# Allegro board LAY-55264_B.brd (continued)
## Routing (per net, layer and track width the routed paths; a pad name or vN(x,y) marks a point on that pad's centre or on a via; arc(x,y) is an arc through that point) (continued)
MIPI_DSI1_DATA0_N: length 64.1
  TOP w0.114: U1.44 36.95,43.61 36.95,43.46 37.35,43.07 37.35,42.54 37.07,42.26 35.99,42.26 35.88,42.14 35.88,41.69 35.99,41.57 37.07,41.57 37.35,41.29 37.35,40.59 37.07,40.3 35.99,40.3 35.88,40.19 35.88,39.73 35.99,39.62 37.07,39.62 37.35,39.33 37.35,38.63 37.07,38.35 35.99,38.35 35.88,38.23 35.88,37.78 35.99,37.66 37.07,37.66 37.35,37.38 37.35,36.68 37.07,36.39 35.99,36.39 35.88,36.28 35.88,35.82 35.99,35.71 37.07,35.71 37.35,35.42 37.35,34.11 37.85,33.61 37.85,33.2 37.11,32.47 37.11,32.31 37.44,31.99 37.6,31.99 38.33,32.72 38.74,32.72 40.69,30.77 40.69,24.61 41.07,24.23 41.64,24.23 41.92,23.94 41.92,22.38 42.04,22.26 42.49,22.26 42.61,22.38 42.61,23.94 42.89,24.23 43.59,24.23 43.88,23.94 43.88,22.38 43.99,22.26 44.45,22.26 44.57,22.38 44.57,23.94 44.85,24.23 45.55,24.23 45.84,23.94 45.84,22.38 45.95,22.26 46.41,22.26 46.52,22.38 46.52,23.94 46.81,24.23 47.51,24.23 47.79,23.94 47.79,22.38 47.91,22.26 48.36,22.26 48.48,22.38 48.48,23.94 48.76,24.23 50.73,24.23 51.23,23.72 51.23,20.49 v2(51.53,20.19)
  BOTTOM w0.114: v2(51.53,20.19) 51.24,20.48 51.24,20.64 51.49,20.9 J2.A2
MIPI_DSI1_DATA0_P: length 64.1
  TOP w0.114: U1.43 36.6,43.26 36.75,43.26 37.06,42.95 37.06,42.66 36.94,42.55 35.87,42.55 35.59,42.27 35.59,41.57 35.87,41.28 36.94,41.28 37.06,41.17 37.06,40.71 36.94,40.59 35.87,40.59 35.59,40.31 35.59,39.61 35.87,39.32 36.94,39.32 37.06,39.21 37.06,38.75 36.94,38.64 35.87,38.64 35.59,38.35 35.59,37.65 35.87,37.37 36.94,37.37 37.06,37.25 37.06,36.8 36.94,36.68 35.87,36.68 35.59,36.4 35.59,35.7 35.87,35.41 36.94,35.41 37.06,35.3 37.06,33.99 37.56,33.49 37.56,33.33 36.82,32.59 36.82,32.19 37.32,31.69 37.72,31.69 38.46,32.43 38.62,32.43 40.4,30.65 40.4,24.49 40.95,23.94 41.52,23.94 41.63,23.82 41.63,22.26 41.92,21.97 42.62,21.97 42.9,22.26 42.9,23.82 43.02,23.94 43.47,23.94 43.59,23.82 43.59,22.26 43.87,21.97 44.57,21.97 44.86,22.26 44.86,23.82 44.97,23.94 45.43,23.94 45.54,23.82 45.54,22.26 45.83,21.97 46.53,21.97 46.81,22.26 46.81,23.82 46.93,23.94 47.38,23.94 47.5,23.82 47.5,22.26 47.78,21.97 48.48,21.97 48.77,22.26 48.77,23.82 48.88,23.94 50.61,23.94 50.94,23.6 50.94,22.45 50.77,22.28 50.77,21.99 50.94,21.82 50.94,21.53 50.77,21.37 50.77,21.07 50.94,20.91 50.94,20.48 v2(50.65,20.19)
  BOTTOM w0.114: v2(50.65,20.19) 50.95,20.48 50.95,20.64 50.69,20.9 J2.A3
MIPI_DSI1_DATA1_N: length 64.2
  TOP w0.114: v2(47.49,18.97) 47.77,19.24 47.9,19.24 48.83,18.31 51.69,18.31 53.73,20.35 53.73,21.54 53.45,21.83 52.67,21.83 52.56,21.94 52.56,22.4 52.67,22.51 53.45,22.51 53.73,22.8 53.73,23.5 53.45,23.78 52.67,23.78 52.56,23.9 52.56,24.35 52.67,24.47 53.45,24.47 53.73,24.75 53.73,30.98 48.32,36.39 47.91,36.39 46.88,35.36 46.72,35.36 46.39,35.68 46.39,35.84 47.43,36.88 47.43,37.28 46.93,37.78 46.53,37.78 44.93,36.18 44.77,36.18 44.45,36.5 44.45,36.67 46.04,38.26 46.04,38.67 45.55,39.16 45.15,39.16 43.55,37.56 43.39,37.56 43.07,37.88 43.07,38.05 44.66,39.65 44.66,40.05 44.17,40.54 43.76,40.54 42.72,39.51 42.56,39.51 42.24,39.83 42.24,39.99 43.28,41.03 43.28,41.43 42.87,41.84 41.4,41.84 38.37,44.88 38.37,45.03 U1.48
  BOTTOM w0.114: v2(47.49,18.97) 47.78,19.25 48.29,19.25 48.84,19.8 48.84,20.64 49.09,20.9 J2.A5
MIPI_DSI1_DATA1_P: length 64.2
  TOP w0.114: v2(47.49,19.85) 47.79,19.55 48,19.55 48.17,19.38 48.34,19.38 48.51,19.56 48.69,19.56 48.84,19.4 48.84,19.24 48.66,19.06 48.66,18.9 48.95,18.61 51.57,18.61 53.44,20.47 53.44,21.42 53.33,21.53 52.55,21.53 52.26,21.82 52.26,22.52 52.55,22.8 53.33,22.8 53.44,22.92 53.44,23.38 53.33,23.49 52.55,23.49 52.26,23.78 52.26,24.47 52.55,24.76 53.33,24.76 53.44,24.87 53.44,27.26 53.29,27.41 53.29,27.72 53.44,27.87 53.44,28.18 53.29,28.33 53.29,28.63 53.44,28.78 53.44,29.09 53.29,29.24 53.29,29.55 53.44,29.7 53.44,30.01 53.29,30.15 53.29,30.46 53.44,30.61 53.44,30.85 48.2,36.1 48.03,36.1 47,35.06 46.59,35.06 46.1,35.56 46.1,35.96 47.14,37 47.14,37.16 46.81,37.48 46.65,37.48 45.05,35.89 44.65,35.89 44.16,36.38 44.16,36.79 45.75,38.38 45.75,38.54 45.43,38.87 45.27,38.87 43.67,37.27 43.27,37.27 42.78,37.76 42.78,38.17 44.37,39.77 44.37,39.93 44.04,40.25 43.88,40.25 42.85,39.21 42.44,39.21 41.95,39.71 41.95,40.11 42.98,41.15 42.98,41.31 42.75,41.55 41.28,41.55 38.16,44.67 38.02,44.67 U1.47
  BOTTOM w0.114: J2.A6 48.29,20.9 48.55,20.64 48.55,19.92 48.17,19.55 47.8,19.55 v2(47.49,19.85)
MIPI_DSI1_DATA2_N: length 63.8
  TOP w0.114: U1.50 39.08,45.73 39.08,45.59 41.15,43.51 43.1,43.51 55.06,31.54 55.06,20.1 52.12,17.15 51.58,17.15 51.47,17.04 51.47,16.21 51.19,15.93 50.49,15.93 50.2,16.21 50.2,17.04 50.09,17.15 49.63,17.15 49.51,17.04 49.51,16.21 49.23,15.93 48.53,15.93 48.24,16.21 48.24,17.04 48.13,17.15 47.67,17.15 47.56,17.04 47.56,16.24 47.27,15.96 46.58,15.96 46.29,16.25 46.29,17.91 46.17,18.02 45.83,18.02 45.7,17.9 45.7,16.29 45.41,16.01 44.72,16.01 44.43,16.29 44.43,17.04 44.32,17.15 43.68,17.15 41.57,19.26 41.39,19.26 v2(41.09,18.97)
  BOTTOM w0.114: v2(41.09,18.97) 41.38,19.25 41.92,19.25 42.44,19.78 42.44,20.64 42.69,20.9 J2.A13
MIPI_DSI1_DATA2_P: length 63.7
  TOP w0.114: U1.49 38.72,45.38 38.87,45.38 41.03,43.22 42.97,43.22 54.77,31.42 54.77,20.22 52,17.45 51.46,17.45 51.18,17.16 51.18,16.33 51.06,16.22 50.61,16.22 50.49,16.33 50.49,17.16 50.21,17.45 49.51,17.45 49.22,17.16 49.22,16.33 49.11,16.22 48.65,16.22 48.54,16.33 48.54,17.16 48.25,17.45 47.55,17.45 47.27,17.16 47.27,16.36 47.15,16.25 46.7,16.25 46.58,16.37 46.58,18.03 46.29,18.32 45.71,18.32 45.41,18.02 45.41,16.41 45.29,16.3 44.84,16.3 44.72,16.41 44.72,17.16 44.44,17.45 43.8,17.45 43,18.25 43,18.41 43.14,18.55 43.14,18.72 42.98,18.88 42.81,18.88 42.67,18.74 42.51,18.74 42.35,18.9 42.35,19.06 42.49,19.2 42.49,19.36 42.33,19.52 42.17,19.52 42.03,19.38 41.87,19.38 41.69,19.55 41.39,19.55 v2(41.09,19.85)
  BOTTOM w0.114: v2(41.09,19.85) 41.4,19.55 41.8,19.55 42.15,19.9 42.15,20.64 41.89,20.9 J2.A14
MIPI_DSI1_DATA3_N: length 64.1
  TOP w0.114: v2(38.69,18.97) 38.99,19.26 39.28,19.26 39.44,19.1 39.44,17.92 42.63,14.73 54.76,14.73 56.21,16.18 56.21,32.37 43.51,45.06 41.01,45.06 39.78,46.29 39.78,46.44 U1.52
  BOTTOM w0.114: J2.A16 40.29,20.9 40.04,20.64 40.04,19.76 39.53,19.25 38.98,19.25 v2(38.69,18.97)
MIPI_DSI1_DATA3_P: length 64.1
  TOP w0.114: v2(38.69,19.85) 38.99,19.55 39.4,19.55 39.74,19.22 39.74,18.04 40.66,17.12 40.82,17.12 41.01,17.31 41.18,17.31 41.34,17.15 41.34,16.99 41.14,16.8 41.14,16.63 42.75,15.03 42.97,15.03 43.17,15.22 43.53,15.22 43.73,15.03 44.07,15.03 44.26,15.22 44.63,15.22 44.82,15.03 45.16,15.03 45.36,15.22 45.72,15.22 45.92,15.03 54.64,15.03 55.92,16.31 55.92,32.24 43.39,44.77 40.89,44.77 39.58,46.09 39.43,46.09 U1.51
  BOTTOM w0.114: J2.A17 39.49,20.9 39.75,20.64 39.75,19.88 39.41,19.55 39,19.55 v2(38.69,19.85)
MIPI_DSI1_TS_INT_B: length 48.3
  TOP w0.137: R7.2 v2(27.99,45.65)
  L4_MIX_2 w0.14: v2(45.89,20.66) 45.64,20.41 45.64,19.73 41.19,15.28 37.09,15.28 35.97,16.41 35.97,20.27 v2(36.3,20.6)
  BOTTOM w0.137: v2(36.3,20.6) 36.3,25.85 27.51,34.64 27.51,45.16 v2(27.99,45.65) ; v2(45.89,20.66) J2.A9
MIPI_DSI1_TS_SCL: length 52.3
  BOTTOM w0.137: v1(11.84,43.81) 13.78,43.81 32.57,25.03 32.57,19.79 37.09,15.28 40.84,15.28 44.58,19.01 44.58,20.32 44.29,20.6 J2.A11
MIPI_DSI1_TS_SDA: length 56.4
  BOTTOM w0.137: J2.A10 45.09,20.56 44.89,20.36 44.89,18.88 40.97,14.96 36.96,14.96 32.26,19.66 32.26,24.89 14.1,43.05 11.63,43.05 11.34,43.35 11.34,45.85 v1(11.84,46.35)
MIPI_DSI_EN: length 30.9
  TOP w0.137: v2(50.04,52.83) 49.66,52.45 U9.2 ; U2.4 v2(32.91,34.3)
  L4_MIX_2 w0.14: v2(50.04,52.83) 49.28,52.07 49.28,46.59 41.04,38.35 36.96,38.35 v2(32.91,34.3)
  BOTTOM w0.137: v2(32.91,34.3) 32.88,34.27 U8.1
PMIC_PG: length 84.5
  TOP w0.137: U6.18 140.76,38.62 140.91,38.46 R74.2 v1(142.63,38.46) ; U5.1 v2(76.6,42.63) 76.2,43.03 76.2,44.15 77.2,45.15 U7.1
  L4_MIX_2 w0.14: v2(76.6,42.63) 76.6,41.61 79.48,38.73 v2(95.63,38.73)
  BOTTOM w0.137: v2(95.63,38.73) 96.77,38.73 97.54,39.5 121.54,39.5 123.06,37.97 136.53,37.97 137.8,36.7 139.95,36.7 141.71,38.46 v1(142.63,38.46)
PRE_COMP_RC: length 1
  TOP w0.254: C87.1 R63.2
SW_CT: length 2.1
  TOP w0.137: C83.1 55.24,69.25 55.24,68.45 55.69,68.01 U10.4
SW_QOD: length 3.3
  TOP w0.508: R70.1 54.28,68.4 54.74,67.94 54.74,67.56 55.25,67.06 U10.5
N20060287: length 7.3
  TOP w0.137: X1.1 36.01,59.5 36.2,59.31 36.2,56.64 C19.1 34.59,55.04 34.59,54.46 U1.15
N20060288: length 4.7
  TOP w0.137: U1.16 34.16,54.18 34.16,55.24 C18.1 32.94,56.47 X1.3
N20069061: length 4.3
  BOTTOM w0.137: J8.B8 112.29,26.94 113.03,27.69 R52.1
N20069073: length 4.2
  BOTTOM w0.137: J8.B9 111.49,26.91 112.01,27.43 R53.1
N20082822: length 1.8
  TOP w0.137: D1.C v2(58.29,38.48)
  BOTTOM w0.137: R25.2 v2(58.29,38.48)
N20082834: length 13.3
  TOP w0.137: Q1.3 v2(54.2,43.31)
  BOTTOM w0.137: R25.1 55.88,37.97 52.2,37.97 50.73,39.44 50.73,40.95 53.09,43.31 v2(54.2,43.31)
N20083165: length 1.8
  TOP w0.137: v2(58.27,36.07) 58.28,36.06 D2.C
  BOTTOM w0.137: R26.2 v2(58.27,36.07)
N20083177: length 19.6
  BOTTOM w0.137: Q2.3 55.21,44.54 54.61,43.94 52.96,43.94 50.42,41.4 50.42,39.12 52.07,37.46 54.99,37.46 R26.1
N20083959: length 3.5
  TOP w0.137: Q3.3 53.33,47.03 v2(52.88,46.58)
  BOTTOM w0.137: R28.2 52.88,46.18 v2(52.88,46.58) 53.2,46.9 Q2.1
N20084103: length 2.7
  TOP w0.137: R29.2 R23.2 Q1.1
N20084118: length 2.6
  TOP w0.137: R31.2 R24.2 Q3.1
N20098940: length 1.8
  TOP w0.137: R37.1 80.17,44.52 80.17,44.37 U5.4
N20105492: length 1.8
  TOP w0.137: D3.C v2(139.88,12.58)
  BOTTOM w0.137: R47.2 v2(139.88,12.58)
N20105494: length 1.8
  TOP w0.137: D4.C v2(139.88,10.17)
  BOTTOM w0.137: R48.2 v2(139.88,10.17)
N20105548: length 3.1
  BOTTOM w0.137: Q4.3 136.67,11.34 R47.1
N20105560: length 11
  TOP w0.137: v2(137.03,10.17) 137.03,13.82 135.74,15.11 v2(135.74,18.96)
  BOTTOM w0.137: R48.1 v2(137.03,10.17) ; Q5.3 v2(135.74,18.96)
N20105562: length 3.3
  BOTTOM w0.137: Q4.1 132.35,10.4 131.95,10.79 131.95,10.79 131.83,10.92 R50.2 R45.2
N20105564: length 2.9
  BOTTOM w0.137: 126.75,17.14 127.89,17.14 127.89,17.66 127.81,17.74 Q6.1
N20105588: length 4.3
  BOTTOM w0.137: Q5.1 R49.2 130.8,18.84 129.87,19.78 Q6.3
N20114256: length 2
  TOP w0.137: R57.2 R58.1 C73.1
N20115373: length 3.9
  TOP w0.137: R65.1 142.6,32.75 R67.2 143.38,32 143.89,32 144.27,31.62 TP15.1
N20115434: length 8
  TOP w0.137: R66.1 142.6,33.76 R68.2 v2(142.62,34.54) ; TP17.1 v2(144.27,29.91)
  BOTTOM w0.137: v2(144.27,29.91) 144.27,31.37 142.62,33.02 v2(142.62,34.54)
N20116336: length 2
  TOP w0.137: U6.19 140.49,39.12 140.6,39.01 141.12,39.01 R75.2
N20169094: length 3.2
  TOP w0.137: R54.2 109.47,19.58 v2(109.14,19.91)
  BOTTOM w0.137: v2(109.14,19.91) 109.49,20.26 J8.A11
N20198038: length 2.9
  BOTTOM w0.137: U8.4 34.18,30.7 34.32,30.57 35.52,30.57 35.69,30.73 R15.1
N20266401: length 2.8
  TOP w0.137: v2(20.23,25.91) 20.23,25.43 20.07,25.27 TP25.1
  BOTTOM w0.137: J1.B10 v2(20.23,25.91)
N20266443: length 3
  TOP w0.137: v2(45.49,26.13) 45.11,26.13 TP27.1
  BOTTOM w0.137: J2.B10 v2(45.49,26.13)
N20266627: length 2.5
  TOP w0.137: v2(85.02,20.62) 85.85,21.45 TP26.1
  BOTTOM w0.137: J7.A10 v2(85.02,20.62)
N20266649: length 2.8
  TOP w0.137: v2(110.29,20.57) TP28.1
  BOTTOM w0.137: TP28.1 v2(110.29,20.57)
N20266684: length 8.6
  TOP w0.137: TP29.1 129.79,37.59 131.32,39.12 U6.52
N20266708: length 8.9
  TOP w0.137: TP30.1 130.81,32 130.81,32.77 130.3,33.27 130.3,37.21 131.21,38.12 U6.54
N20266714: length 6.2
  TOP w0.137: U6.55 131.34,37.62 130.81,37.08 130.81,33.66 TP31.1
N20267097: length 3.5
  TOP w0.137: U6.56 131.61,37.12 131.32,36.83 131.32,34.8 TP32.1
N20272842: length 1.8
  TOP w0.137: D7.C v2(58.32,41.54)
  BOTTOM w0.137: v2(58.32,41.54) 57.42,41.54 R87.2
N20272854: length 2.9
  BOTTOM w0.137: R87.1 53.48,41.53 Q8.3
N20272867: length 2.5
  TOP w0.137: R88.1 55.09,39.62 55.24,39.78 v2(55.63,39.78)
  BOTTOM w0.137: v2(55.63,39.78) 55.36,39.51 Q8.1
N20273152: length 1.8
  TOP w0.137: D8.C 58.35,46.39 v2(58.32,46.35)
  BOTTOM w0.137: R89.2 v2(58.32,46.35)
N20273623: length 1.8
  TOP w0.137: D9.C v2(139.85,14.99)
  BOTTOM w0.137: R90.2 v2(139.85,14.99)
N20273625: length 2
  TOP w0.137: D10.C v2(139.97,21.05)
  BOTTOM w0.137: R91.2 139.74,20.83 v2(139.97,21.05)
N20273637: length 2.9
  BOTTOM w0.137: R90.1 137.04,15.86 Q9.3
N20273680: length 1.4
  BOTTOM w0.137: R92.1 131.9,14.93 Q9.1
N20273951: length 1.9
  TOP w0.137: D11.C v2(139.97,19.4)
  BOTTOM w0.137: R93.2 v2(139.97,19.4)
N20274335: length 1.8
  TOP w0.137: v2(58.32,48.77) 58.36,48.81 D12.C
  BOTTOM w0.137: R94.2 v2(58.32,48.77)
N20274920: length 1.8
  TOP w0.137: D13.C v2(139.85,17.41)
  BOTTOM w0.137: R95.2 v2(139.85,17.41)
N20275554: length 1.8
  TOP w0.137: D14.C 59.15,43.94 v2(58.32,43.94)
  BOTTOM w0.137: v2(58.32,43.94) R96.2
N20319150: length 2.9
  TOP w0.137: R99.1 J13.2
N20319151: length 2.8
  TOP w0.137: R107.1 J13.4
N20319153: length 2.8
  TOP w0.137: R109.1 J13.6
N20319312: length 3.2
  TOP w0.137: R108.2 J13.5
N20319313: length 3.2
  TOP w0.137: R100.2 J13.3
N20319314: length 3.2
  TOP w0.137: R98.2 J13.1
N20319786: length 2.8
  TOP w0.137: R104.2 J14.1
N20319788: length 2.8
  TOP w0.137: R101.1 127.89,3.94
N20319806: length 2.8
  TOP w0.137: R105.2 J14.3
N20319808: length 2.8
  TOP w0.137: R102.1 127.89,6.48
N20319814: length 2.8
  TOP w0.137: R106.2 130.43,9.02
N20319816: length 2.8
  TOP w0.137: R103.1 127.89,9.02
N20331689: length 3.5
  TOP w0.137: U7.4 78.5,55.86 R112.1 R110.2 R111.2
N20347583: length 1.8
  TOP w0.137: U9.4 v2(51.96,51.8)
  BOTTOM w0.137: R69.1 52.45,51.82 52.43,51.8 v2(51.96,51.8)
N2022936611: length 9
  TOP w0.137: v2(143.82,41.03) 143.82,41.33 TP33.1 ; v2(138.15,37.29) U6.12
  BOTTOM w0.137: v2(138.15,37.29) 139.58,37.29 142.57,40.28 143.07,40.28 v2(143.82,41.03)
N2022936612: length 6.7
  TOP w0.137: U6.13 138.65,35.82 138.81,35.66 139,35.66 139.61,35.05 143.76,35.05 TP34.1
N2022936613: length 8.1
  TOP w0.137: U6.14 139.15,35.9 139.61,35.45 143.14,35.45 143.89,36.19 143.89,37.97 TP35.1
N2022936614: length 8.9
  TOP w0.137: U6.15 140.39,37.12 140.53,36.98 140.53,36.43 141.18,35.78 143.03,35.78 143.57,36.32 143.57,38.91 143.77,39.11 143.77,39.76 TP36.1
N2022936615: length 9.4
  TOP w0.137: U6.16 140.51,37.62 140.84,37.29 140.84,36.56 141.31,36.09 142.9,36.09 143.26,36.45 143.26,39.04 143.45,39.24 143.45,40.19 TP37.1
N2022936623: length 5.5
  TOP w0.137: U6.24 140.5,41.62 140.69,41.8 143.15,41.8 144.15,42.8 TP38.1
N2022936624: length 3.2
  TOP w0.137: TP39.1 142.07,42.12 U6.25
N2022936625: length 5.1
  TOP w0.137: TP40.1 141.3,42.62 U6.26
N2022936626: length 3.2
  TOP w0.137: U6.27 140.65,43.12 TP41.1
N2022936627: length 6.5
  TOP w0.137: TP42.1 142.88,46.48 140.84,44.45 140.84,43.94 140.52,43.62 U6.28
N2022936628: length 6.2
  TOP w0.137: U6.29 139.15,44.79 139.45,45.09 140.97,45.09 TP43.1
N2022936629: length 4.8
  TOP w0.137: U6.30 138.65,44.8 139.25,45.4 140.27,45.4 TP44.1
N2022936630: length 8.5
  TOP w0.137: U6.31 138.15,44.8 141.35,48.01 142.37,48.01 143.51,49.15 TP45.1
N2022936631: length 6.3
  TOP w0.137: TP46.1 141.73,48.83 137.65,44.75 U6.32
N2022936633: length 9.5
  TOP w0.137: U6.34 136.65,44.83 138.68,46.86 138.68,48.2 140.65,50.16 TP47.1
N2022936634: length 8.8
  TOP w0.137: U6.35 136.15,44.84 138.37,47.06 138.37,48.33 TP48.1

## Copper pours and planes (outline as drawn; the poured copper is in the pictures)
GND on TOP (solid shape): 15.29,64.85 15.29,57.71 15.28,57.65 15.28,57.59 15.28,57.37 15.28,57.31 15.29,57.25 15.29,56.72 15.49,56.52 15.49,55.45 13.69,55.45 13.51,55.63 13.51,60.45 13.44,60.45 13.44,61.98 13.51,61.98 13.51,64.48 13.51,64.85 13.64,64.97 15.16,64.97
GND on BOTTOM (solid shape): 13.67,34.54 13.67,32.99 13.44,32.77 11.71,32.77 11.56,32.92 11.56,34.52 11.76,34.72 13.49,34.72
GND on BOTTOM (solid shape): 15.57,30.91 15.57,29.29 15.42,29.13 13.79,29.13 13.59,29.34 13.59,30.94 13.69,31.04 15.44,31.04
GND on BOTTOM (solid shape): 22.1,30.99 22.1,29.34 21.89,29.13 20.27,29.13 20.07,29.34 20.07,30.99 20.32,31.24 21.84,31.24
GND on BOTTOM (solid shape): 25.27,30.99 25.27,29.34 25.07,29.13 23.44,29.13 23.24,29.34 23.24,30.99 23.49,31.24 25.02,31.24
GND on BOTTOM (solid shape): 40.83,31.04 40.83,29.29 40.68,29.13 39.06,29.13 38.85,29.34 38.85,30.99 39.11,31.24 40.63,31.24
GND on BOTTOM (solid shape): 43.42,30.99 43.42,29.34 43.22,29.13 41.6,29.13 41.39,29.34 41.39,30.99 41.65,31.24 43.17,31.24
GND on BOTTOM (solid shape): 47.36,30.95 47.36,29.34 47.16,29.13 45.53,29.13 45.33,29.34 45.33,30.85 45.59,31.12 47.19,31.12
GND on BOTTOM (solid shape): 49.86,30.96 49.86,29.36 49.63,29.13 48.31,29.13 48.18,29.26 48.18,30.94 48.31,31.06 49.76,31.06
GND on TOP: 110.36,52.36 110.36,39.3 111.12,38.55 111.12,38.31 111.11,38.31 111.11,37.13 113.22,35.02 131.86,35.02 131.86,46.45 130.3,48.01 130.3,49.15 126.53,52.93 110.93,52.93
GND on TOP: 139.95,22.86 143.51,22.86 143.64,22.99 143.64,30.23 143.51,30.35 139.95,30.35 139.7,30.1 139.7,23.11
GND on TOP: 52.78,64.08 52.6,63.91 52.6,62.2 52.83,61.98 55.32,61.98 55.58,62.23 55.58,63.91 55.4,64.08
GND on TOP: 120.4,67.06 124.59,67.06 124.84,66.8 124.84,61.85 124.46,61.47 120.4,61.47 120.14,61.72 120.14,66.8
GND on TOP: 101.93,48.59 102.48,48.59 109,42.07 109,39.21 110.25,37.96 110.25,36.36 112.53,34.07 114.13,34.07 121.92,26.29 121.92,2.74 75.58,2.74 75.58,14.09 75.74,14.25 76.48,14.25 76.15,14.58 75.58,14.58 75.58,38.06 85.67,48.15 86.46,48.15 86.5,48.2 86.51,48.24 86.49,48.34 86.4,48.39 86.25,48.39 87.25,48.39 92.16,43.48 92.5,43.48 96.27,47.25 100.03,47.25 100.24,47.46 100.8,47.46 ; 9 cut-outs
GND on TOP: 133.93,32.64 134.24,32.64 135.15,31.72 135.15,31.47 134.26,30.58 134.01,30.58 133.07,31.52 133.07,31.78
GND on TOP: 111.25,66.29 113.03,68.07 113.03,68.33 113.41,68.71 113.92,68.71 115.19,67.44 115.19,67.06 112.9,64.77 112.52,64.77 111.25,66.04
GND on TOP: 132.44,35.26 133.1,35.26 133.3,35.46 133.3,36.88 133.48,37.06 133.48,37.49 134.11,38.13 138.23,38.13 138.23,39.7 138.3,39.78 139.19,39.78 139.19,40.51 138.33,40.51 138.23,40.61 138.23,42.65 133.76,42.65 133.6,42.49 133.6,38.61 132.49,37.49 132.51,37.46 132.51,35.79 132.33,35.61 132.33,35.36
GND on TOP: 129.16,65.91 130.3,65.91 130.68,66.29 134.24,66.29 135.38,65.15 139.45,65.15 139.95,65.66 139.95,69.09 139.19,69.85 129.29,69.85 129.03,69.6 129.03,66.04
GND on TOP: 20.37,48.77 27.94,48.77 27.94,47.78 30.68,47.78 30.68,48.44 35.64,43.48 35.98,43.48 39.75,47.25 40.23,47.25 40.23,45.59 40.67,45.16 42.21,45.16 42.21,45.42 41.91,45.72 41.91,46.56 41.61,46.86 41.61,47.17 41.68,47.25 46.23,47.25 65.41,28.07 65.41,2.49 9.37,2.49 9.37,37.77 ; 3 cut-outs
GND on TOP: 138.93,50.67 138.93,54.87 138.81,54.99 136.17,54.99 135.97,54.79 135.97,50.6 136.14,50.42 138.68,50.42
GND on TOP: 128.52,24.77 128.52,20.83 128.91,20.45 133.48,20.45 134.11,21.08 134.11,29.72 133.99,29.84 129.79,29.84 129.54,29.59 129.54,25.78
GND on TOP: 58.04,66.75 59.69,66.75 59.99,67.06 64.39,67.06 64.9,67.56 64.9,71.09 64.64,71.35 59.79,71.35 59.56,71.12 59.56,69.85 60.2,69.85 60.32,69.72 60.32,68.45 59.23,67.36 58.04,67.36
GND on BOTTOM: 1.27,79.76 65.41,79.76 65.41,1.27 1.27,1.27 1.27,14.99 55.24,14.99 55.24,35.05 18.03,35.05 17.4,35.69 9.4,35.69 8.74,36.35 8.74,40.03 8.74,36.35 9.4,35.69 9.75,35.69 9.75,38.28 9.78,38.4 9.85,38.51 11.37,40.03 12.16,40.03 12.13,39.91 12.06,39.82 11.42,39.17 11.4,39.1 11.46,39.06 11.51,39.06 11.53,39.07 11.67,39.16 11.84,39.19 12.29,38.73 11.84,38.28 11.66,38.31 11.51,38.41 11.11,38.41 10.71,38.02 10.71,35.69 17.4,35.69 18.03,35.05 21.35,35.05 21.46,35.14 21.43,35.27 15.33,41.37 15.47,41.5 15.47,42.57 13.92,44.12 13.54,44.12 13.36,44.3 13.36,46.28 13.74,46.66 13.54,46.86 9.07,46.86 8.74,47.19 8.74,65.38 1.27,65.38 ; 1 cut-out
GND on BOTTOM: 66.67,79.76 146.05,79.76 146.05,1.27 67.31,1.27 67.31,14.73 94.13,14.73 94.51,14.35 94.51,12.85 95.3,12.07 95.3,9.17 96.44,8.03 99.95,8.03 100.43,8.51 100.43,13.89 101.27,14.73 120.9,14.73 120.9,32 94.16,32 94.44,31.72 94.44,31.42 94.23,31.22 92.99,31.22 92.2,32 66.67,32 ; 2 cut-outs
GND on L2_GND_1, L5_GND_2: 1.27,79.76 146.05,79.76 146.05,1.27 1.27,1.27
GND on L3_MIX_1: 1.65,67.82 7.62,67.82 8.76,66.67 21.72,66.67 21.72,57.02 24.77,53.98 38.86,53.98 39.5,53.34 43.05,53.34 43.81,54.1 43.81,57.28 47.5,60.96 53.85,60.96 53.85,78.23 52.32,79.76 1.27,79.76 1.27,68.2
GND on L3_MIX_1: 66.67,79.76 146.05,79.76 146.05,1.27 66.67,1.27
GND on L4_MIX_2: 10.79,79.76 65.02,79.76 65.02,46.1 49.53,46.1 49.53,53.59 40.31,53.59 40.31,53.72 38.61,55.42 37.06,55.42 36.75,55.12 36.75,53.98 38.58,52.15 38.61,52.15 38.61,48.79 38.43,48.62 32.66,48.62 32.51,48.77 32.51,51.36 33.15,51.99 33.15,53.75 32.26,54.64 26.49,54.64 26.06,54.2 24.97,54.2 24.77,54.41 24.77,58.01 23.04,59.74 17.17,59.74 14.78,57.35 13.26,57.35 10.79,59.82
GND on L4_MIX_2: 68.96,79.76 146.05,79.76 146.05,58.29 103.12,58.29 103.12,51.05 99.39,51.05 97.1,53.34 97.1,55.37 95.33,57.15 92.08,57.15 89.97,55.04 88.04,55.04 87.07,54.08 83.46,54.08 77.85,59.69 77.85,66.93 75.95,68.83 68.96,68.83 ; 1 cut-out
VCC_1V0_SER on TOP (solid shape): 18.15,59.17 18.94,59.17 19.69,58.42 19.69,55.78 19.35,55.45 15.93,55.45 15.85,55.52 15.85,56.39 16.33,56.87 16.33,58.09 15.6,58.83 15.6,60.15 17.17,60.15
VCC_1V0_SER on L4_MIX_2: 20.78,54.91 25.02,50.67 29.79,50.67 31.06,51.94 31.37,51.94 31.98,51.33 31.98,48.11 31.27,47.4 21.34,47.4 16.64,52.1 16.64,57.84 17.53,58.72 19.61,58.72 20.78,57.56
VCC_1V8_LVDS on TOP (solid shape): 89.84,19.79 89.84,18.87 89.59,18.62 89.28,18.62 89.05,18.85 88.01,18.85 87.83,19.02 87.83,20.02 88.01,20.19 89.43,20.19
VCC_1V8_LVDS on TOP (solid shape): 115.1,19.57 115.1,18.87 114.85,18.62 114.54,18.62 114.32,18.85 113.27,18.85 113.1,19.02 113.1,20.18 113.36,20.45 114.22,20.45
VCC_1V8_LVDS on BOTTOM (solid shape): 89.23,22.8 89.23,20.4 89.84,19.79 89.84,18.87 89.58,18.62 88.26,18.62 88.03,18.85 88.03,22.82 88.08,22.87 89.15,22.87
VCC_1V8_LVDS on BOTTOM (solid shape): 114.49,22.8 114.49,20.18 115.1,19.57 115.1,18.87 114.85,18.62 113.53,18.62 113.3,18.85 113.3,22.82 113.35,22.87 114.41,22.87
VCC_1V8_LVDS on TOP: 133.15,48.97 135.51,48.97 135.51,55.02 135.03,55.5 132.92,55.5 132.46,55.04 132.46,49.66
VCC_1V8_LVDS on BOTTOM: 132.59,50.16 135.26,50.16 135.51,50.42 135.51,55.02 135.03,55.5 132.92,55.5 132.46,55.04 132.46,50.29
VCC_1V8_LVDS on L3_MIX_1: 129.54,12.07 132.21,9.4 132.21,3.3 132.59,2.92 135.26,2.92 135.76,3.43 135.76,12.07 133.6,14.22 131.06,14.22 129.54,12.7
VCC_1V8_LVDS on L3_MIX_1: 69.98,36.68 69.98,26.8 77.09,26.8 77.09,22.48 84.33,22.48 84.33,18.67 115.82,18.67 127.64,30.48 127.64,37.08 139.32,37.08 139.32,59.18 102.62,59.18 102.62,52.96 101.73,52.07 100.46,52.07 98.3,54.23 98.3,56.52 95.63,59.18 88.14,59.18 86.44,57.48 86.44,53.92 85.47,52.96 81.38,52.96 80.52,53.82 80.52,55.98 80.19,56.31 78.16,56.31 77.72,55.88 77.72,39.98 75.18,37.44 70.74,37.44
VCC_1V8_MIPI on TOP (solid shape): 13.21,58.08 13.18,58.07 13.14,58.02 13.13,57.96 13.13,57.76 13.14,57.7 13.18,57.66 13.21,57.64 13.21,55.58 13.08,55.45 11.25,55.45 11.02,55.68 11.02,57.81 11.73,58.52 11.73,60.02 11.86,60.15 13.21,60.15
VCC_1V8_MIPI on BOTTOM (solid shape): 24.61,28.4 24.61,26.87 24.43,26.69 24.43,23.65 24.38,23.6 23.32,23.6 23.24,23.67 23.24,26.09 22.58,26.75 22.58,28.24 22.86,28.52 24.49,28.52
VCC_1V8_MIPI on BOTTOM (solid shape): 49.78,28.32 49.78,26.78 49.7,26.69 49.7,23.65 49.65,23.6 48.58,23.6 48.5,23.67 48.5,26.25 47.88,26.87 47.88,28.37 48.03,28.52 49.58,28.52
VCC_1V8_MIPI on L3_MIX_1: 1.91,65.66 17.78,65.66 19.18,67.06 19.18,72.77 19.43,73.02 21.21,73.02 21.46,72.77 21.46,56.39 24.38,53.47 38.61,53.47 39.37,52.7 43.18,52.7 44.45,53.98 44.45,57.15 47.62,60.32 53.85,60.32 53.85,27.05 47.62,27.05 47.62,29.08 26.29,29.08 26.29,26.8 22.35,26.8 22.35,29.08 1.91,29.08
VCC_3V3_LVDS on TOP (solid shape): 83.31,19.91 83.31,18.75 83.19,18.62 82.88,18.62 82.65,18.85 81.61,18.85 81.43,19.02 81.43,20.02 81.61,20.19 83.03,20.19
VCC_3V3_LVDS on TOP (solid shape): 108.7,19.77 108.7,18.87 108.45,18.62 108.14,18.62 107.92,18.85 106.87,18.85 106.7,19.02 106.7,20.02 106.87,20.19 108.28,20.19
VCC_3V3_LVDS on BOTTOM (solid shape): 82.83,22.8 82.83,20.45 83.44,19.84 83.44,18.87 83.18,18.62 81.86,18.62 81.63,18.85 81.63,22.82 81.68,22.87 82.75,22.87
VCC_3V3_LVDS on BOTTOM (solid shape): 108.09,22.8 108.09,20.38 108.7,19.77 108.7,18.87 108.45,18.62 107.13,18.62 106.9,18.85 106.9,22.82 106.95,22.87 108.01,22.87
VCC_3V3_LVDS on TOP: 136.4,32.38 136.02,32 136.02,29.84 135.13,28.96 135.13,22.1 135.38,21.84 138.81,21.84 139.07,22.1 139.07,32.38
VCC_3V3_LVDS on L3_MIX_1: 69.98,26.29 69.98,9.65 145.67,9.65 145.67,42.04 139.83,42.04 139.83,37.08 139.45,36.7 128.02,36.7 128.02,30.1 116.08,18.16 110.49,18.16 110.49,20.32 107.06,20.32 107.06,18.16 83.82,18.16 83.82,21.97 76.58,21.97 76.58,26.29
VCC_3V3_MIPI on BOTTOM (solid shape): 43.42,28.22 43.42,26.34 43.3,26.21 43.3,23.65 43.25,23.6 42.18,23.6 42.1,23.67 42.1,26.77 42,26.87 41.62,26.87 41.4,27.09 41.4,28.33 41.6,28.52 43.12,28.52
VCC_3V3_MIPI on BOTTOM (solid shape): 18.16,34.04 18.16,26.29 18.03,26.16 18.03,23.65 17.98,23.6 16.92,23.6 16.84,23.67 16.84,26.11 16.13,26.82 16.13,31.62 15.75,32 14.48,32 14.22,32.26 14.22,32.89 14.22,33.91 14.22,34.57 14.38,34.72 17.48,34.72
VCC_3V3_MIPI on L4_MIX_2: 40.64,22.86 64.14,22.86 64.14,45.59 49.28,45.59 39.88,36.2 11.56,36.2 11.56,30.35 40.39,30.35 40.64,30.1 ; 1 cut-out
VCC_5V0_LVDS on TOP (solid shape): 80.7,20.02 80.7,18.97 80.57,18.85 79.65,18.85 79.43,18.62 78.87,18.62 78.61,18.87 78.61,19.91 78.89,20.19 80.52,20.19
VCC_5V0_LVDS on TOP (solid shape): 105.96,20.02 105.96,18.97 105.83,18.85 104.92,18.85 104.69,18.62 104.13,18.62 103.88,18.87 103.88,19.78 104.29,20.19 105.78,20.19
VCC_5V0_LVDS on BOTTOM (solid shape): 80.42,22.82 80.42,18.85 80.19,18.62 78.87,18.62 78.61,18.87 78.61,19.91 79.22,20.52 79.22,22.8 79.3,22.87 80.37,22.87
VCC_5V0_LVDS on BOTTOM (solid shape): 105.68,22.82 105.68,18.85 105.45,18.62 104.13,18.62 103.88,18.87 103.88,19.78 104.49,20.39 104.49,22.8 104.56,22.87 105.63,22.87
VCC_5V0_LVDS on TOP: 136.09,48.01 137.54,48.01 137.74,47.8 137.74,46.69 135.89,44.83 135.89,43.94 135.51,43.94 135.51,45.21 135.76,45.47 135.76,45.59 135.94,45.77 135.94,47.85
VCC_5V0_LVDS on TOP: 135,36.83 135,35.94 134.8,35.74 134.8,34.72 134.98,34.54 134.98,33.4 135.76,32.61 136.14,32.61 136.47,32.94 136.47,33.43 135.64,34.26 135.64,34.95 135.28,35.31 135.28,36.86 135.26,36.88 135.05,36.88
VCC_5V0_LVDS on TOP, BOTTOM: 110.49,53.47 110.74,53.21 116.2,53.21 116.2,57.4 115.7,57.91 111.28,57.91 110.49,57.12
VCC_5V0_LVDS on L4_MIX_2: 111.38,57.91 144.65,57.91 144.65,6.1 78.61,6.1 78.61,20.57 83.24,20.57 84.07,19.74 84.07,13.34 99.57,13.34 102.67,16.43 102.67,16.92 102.62,16.97 102.62,19.51 103.17,20.07 105.92,20.07 105.92,13.34 128.52,13.34 128.52,36.7 130.68,38.86 130.68,40.64 123.19,40.64 123.19,49.4 111.38,49.4
VCC_5V0_MIPI on BOTTOM (solid shape): 15.62,28.35 15.62,23.65 15.57,23.6 14.5,23.6 14.43,23.67 14.43,26.77 14.33,26.87 13.74,26.87 13.59,27.03 13.59,28.35 13.77,28.52 15.44,28.52
VCC_5V0_MIPI on BOTTOM (solid shape): 40.88,28.35 40.88,23.65 40.83,23.6 39.77,23.6 39.69,23.67 39.69,26.77 39.59,26.87 39.01,26.87 38.85,27.03 38.85,28.35 39.03,28.52 40.71,28.52
VCC_5V0_MIPI on L4_MIX_2: 40,29.46 40,22.89 11.56,22.89 11.56,28.52 23.49,28.52 24.43,29.46
VCC_12V0 on TOP: 117.09,67.56 124.59,67.56 124.71,67.69 124.71,74.04 124.33,74.42 122.17,74.42 121.92,74.17 121.92,71.55 121.11,70.74 117.35,70.74 116.97,70.36 116.97,67.69
VCC_12V0_DESCONN on TOP: 111.51,74.17 120.9,74.17 121.16,73.91 121.16,71.5 120.78,71.12 115.19,71.12 108.99,64.92 106.55,64.92 106.02,65.46 106.02,68.68
VCC_12V0_DESCONN on BOTTOM: 114.81,70.74 121.16,70.74 121.54,71.12 121.54,73.66 121.03,74.17 111.51,74.17 105.92,68.58 105.92,65.53 106.55,64.9 108.97,64.9
VCC_12V0_EXT on TOP, BOTTOM: 128.83,65.48 133.91,65.48 135.51,63.88 139.57,63.88 140.08,63.37 140.08,59.82 139.7,59.44 127.13,59.44 125.09,61.47 125.09,74.17 125.35,74.42 128.02,74.42 128.65,73.79 128.65,65.66
VCC_12V0_LVDS on TOP (solid shape): 112.36,20.02 112.36,18.97 112.23,18.85 111.28,18.85 111.05,18.62 110.53,18.62 110.28,18.87 110.28,19.91 110.56,20.19 112.18,20.19
VCC_12V0_LVDS on TOP (solid shape): 87.1,20.02 87.1,18.97 86.97,18.85 86.05,18.85 86,18.8 85.98,18.8 85.98,18.77 85.83,18.62 85.37,18.62 85.19,18.8 85.19,19.89 85.5,20.19 86.92,20.19
VCC_12V0_LVDS on BOTTOM (solid shape): 86.82,22.82 86.82,18.85 86.59,18.62 85.27,18.62 85.01,18.87 85.01,19.91 85.62,20.52 85.62,22.8 85.7,22.87 86.77,22.87
VCC_12V0_LVDS on BOTTOM (solid shape): 112.08,22.82 112.08,18.85 111.85,18.62 110.53,18.62 110.28,18.87 110.28,19.91 110.89,20.52 110.89,22.8 110.96,22.87 112.03,22.87
VCC_12V0_LVDS on TOP: 132.38,40.26 132.38,39.47 131.17,39.47 129.41,37.72 129.41,33.4 127.76,31.75 127.76,20.83 127.38,20.45 123.57,20.45 123.32,20.7 123.32,27.18 119.76,30.73 119.76,34.8 120.27,35.31 124.46,35.31 125.35,36.2 125.35,36.96 128.65,40.26
VCC_12V0_LVDS on TOP, BOTTOM: 119.38,61.47 119.63,61.72 119.63,65.15 119.38,65.41 114.17,65.41 113.41,64.64 113.41,61.85 113.79,61.47
VCC_12V0_LVDS on L4_MIX_2: 109.6,65.91 119.25,65.91 119.53,65.63 119.53,58.29 110.74,58.29 110.74,49.02 122.81,49.02 122.81,40.26 130.2,40.26 130.2,38.91 128.14,36.86 128.14,13.84 101.24,13.84 101.24,19.38 101.7,19.84 101.7,20.65 101.24,21.11 101.24,22.5 100,23.75 96.55,23.75 95.35,22.56 95.35,21.97 94.77,21.39 94.77,18.39 94.36,17.98 93.37,17.98 93.07,17.68 93.07,14.5 92.41,13.84 85.09,13.84 85.09,25.88 102.59,25.88 103.38,26.67 103.38,62.1 107.7,62.1 108.2,62.61 108.2,64.52
VCC_12V0_MIPI on BOTTOM (solid shape): 22.03,28.35 22.03,23.65 21.98,23.6 20.92,23.6 20.84,23.67 20.84,26.7 20.64,26.9 20.24,26.9 20.07,27.08 20.07,28.37 20.22,28.52 21.86,28.52
VCC_12V0_MIPI on BOTTOM (solid shape): 47.3,28.35 47.3,23.65 47.25,23.6 46.18,23.6 46.1,23.67 46.1,26.7 45.9,26.9 45.51,26.9 45.33,27.08 45.33,28.37 45.48,28.52 47.12,28.52
VCC_12V0_MIPI on TOP: 58.04,66.42 59.41,66.42 59.54,66.55 64.14,66.55 64.14,59.05 62.86,57.78 57.02,57.78 56.52,58.29 56.52,62.99 58.04,64.52
VCC_12V0_MIPI on L3_MIX_1: 1.91,28.58 46.99,28.58 46.99,25.4 54.74,25.4 54.74,62.36 55.37,62.99 64.14,62.99 64.77,62.36 64.77,9.27 1.91,9.27
VCC_12V0_SER on TOP: 48.56,69.09 50.93,69.09 52.2,67.82 52.2,67.31 52.58,66.93 54.1,66.93 54.61,66.42 56.52,66.42 56.52,65.41 55.5,64.39 50.65,64.39 50.09,64.95 48.69,64.95 48.21,65.43 48.21,68.73
VCC_12V0_SER on BOTTOM: 48.74,64.9 49.91,64.9 50.29,64.52 53.34,64.52 53.98,65.15 53.98,67.36 53.57,67.77 48.72,67.77 48.13,67.18 48.13,65.51
VCC_12V0_SER on L3_MIX_1: 48.51,67.69 53.59,67.69 54.23,67.06 54.23,64.77 53.85,64.39 50.27,64.39 49.81,64.85 48.79,64.85 48.21,65.43 48.21,67.39
VCC_12V0_SER on L4_MIX_2: 48.39,67.69 53.59,67.69 54.23,67.06 54.23,64.77 53.85,64.39 50.24,64.39 49.78,64.85 48.64,64.85 48.13,65.35 48.13,67.44
(no net) on TOP: 78.61,19.91 78.61,18.87 78.87,18.62 79.43,18.62 79.65,18.85 80.57,18.85 80.7,18.97 80.7,20.02 80.52,20.19 78.89,20.19
(no net) on TOP: 108.45,18.62 108.14,18.62 107.92,18.85 106.87,18.85 106.7,19.02 106.7,20.02 106.87,20.19 108.28,20.19 108.7,19.77 108.7,18.87
(no net) on TOP: 103.88,19.78 103.88,18.87 104.13,18.62 104.69,18.62 104.92,18.85 105.83,18.85 105.96,18.97 105.96,20.02 105.78,20.19 104.29,20.19
(no net) on TOP: 13.44,55.7 13.44,61.98 13.51,61.98 13.51,64.85 13.64,64.97 15.16,64.97 15.29,64.85 15.29,56.72 15.49,56.52 15.49,55.45 13.69,55.45
(no net) on TOP: 15.85,55.52 15.85,56.39 16.33,56.87 16.33,58.09 15.54,58.88 15.54,60.15 17.17,60.15 18.15,59.17 18.94,59.17 19.69,58.42 19.69,55.78 19.35,55.45 15.93,55.45
(no net) on TOP: 110.28,19.91 110.28,18.87 110.53,18.62 111.05,18.62 111.28,18.85 112.23,18.85 112.36,18.97 112.36,20.02 112.18,20.19 110.56,20.19
(no net) on TOP: 13.21,60.15 11.86,60.15 11.73,60.02 11.73,58.52 11.02,57.81 11.02,55.68 11.25,55.45 13.08,55.45 13.21,55.58
(no net) on TOP: 89.59,18.62 89.28,18.62 89.05,18.85 88.01,18.85 87.83,19.02 87.83,20.02 88.01,20.19 89.43,20.19 89.84,19.79 89.84,18.87
(no net) on TOP: 114.85,18.62 114.54,18.62 114.32,18.85 113.27,18.85 113.1,19.02 113.1,20.18 113.36,20.45 114.22,20.45 115.1,19.57 115.1,18.87
(no net) on TOP: 83.19,18.62 82.88,18.62 82.65,18.85 81.61,18.85 81.43,19.02 81.43,20.02 81.61,20.19 83.03,20.19 83.31,19.91 83.31,18.75
(no net) on TOP: 85.19,19.89 85.19,18.8 85.37,18.62 85.83,18.62 86.05,18.85 86.97,18.85 87.1,18.97 87.1,20.02 86.92,20.19 85.5,20.19
(no net) on BOTTOM: 39.77,23.6 40.83,23.6 40.88,23.65 40.88,28.35 40.71,28.52 39.03,28.52 38.85,28.35 38.85,27.03 39.01,26.87 39.59,26.87 39.69,26.77 39.69,23.67
(no net) on BOTTOM: 42.18,23.6 43.25,23.6 43.3,23.65 43.3,26.21 43.42,26.34 43.42,28.22 43.12,28.52 41.6,28.52 41.4,28.33 41.4,27.09 41.62,26.87 42,26.87 42.1,26.77 42.1,23.67
(no net) on BOTTOM: 11.56,32.92 11.71,32.77 13.44,32.77 13.67,32.99 13.67,34.54 13.49,34.72 11.76,34.72 11.56,34.52
(no net) on BOTTOM: 46.18,23.6 47.25,23.6 47.3,23.65 47.3,28.35 47.12,28.52 45.48,28.52 45.33,28.37 45.33,27.08 45.51,26.9 45.9,26.9 46.1,26.7 46.1,23.67
(no net) on BOTTOM: 43.42,29.34 43.42,30.99 43.17,31.24 41.65,31.24 41.39,30.99 41.39,29.34 41.6,29.13 43.22,29.13
(no net) on BOTTOM: 16.92,23.6 17.98,23.6 18.03,23.65 18.03,26.16 18.16,26.29 18.16,34.04 17.48,34.72 14.38,34.72 14.22,34.57 14.22,32.26 14.48,32 15.75,32 16.13,31.62 16.13,26.82 16.84,26.11 16.84,23.67
(no net) on BOTTOM: 13.59,30.94 13.59,29.34 13.79,29.13 15.42,29.13 15.57,29.29 15.57,30.91 15.44,31.04 13.69,31.04
(no net) on BOTTOM: 47.36,29.34 47.36,30.95 47.19,31.12 45.59,31.12 45.33,30.85 45.33,29.34 45.53,29.13 47.16,29.13
(no net) on BOTTOM: 48.58,23.6 49.65,23.6 49.7,23.65 49.7,26.69 49.78,26.78 49.78,28.32 49.58,28.52 48.03,28.52 47.88,28.37 47.88,26.87 48.5,26.25 48.5,23.67
(no net) on BOTTOM: 48.18,30.94 48.18,29.26 48.31,29.13 49.63,29.13 49.86,29.36 49.86,30.96 49.76,31.06 48.31,31.06
(no net) on BOTTOM: 40.83,31.04 40.63,31.24 39.11,31.24 38.85,30.99 38.85,29.34 39.06,29.13 40.68,29.13 40.83,29.29
(no net) on BOTTOM: 23.32,23.6 24.38,23.6 24.43,23.65 24.43,26.69 24.61,26.87 24.61,28.4 24.49,28.52 22.86,28.52 22.58,28.24 22.58,26.75 23.24,26.09 23.24,23.67
(no net) on BOTTOM: 108.01,22.87 106.95,22.87 106.9,22.82 106.9,18.85 107.13,18.62 108.45,18.62 108.7,18.87 108.7,19.77 108.09,20.38 108.09,22.8
(no net) on BOTTOM: 20.92,23.6 21.98,23.6 22.03,23.65 22.03,28.35 21.86,28.52 20.22,28.52 20.07,28.37 20.07,27.08 20.24,26.9 20.64,26.9 20.84,26.7 20.84,23.67
(no net) on BOTTOM: 114.41,22.87 113.35,22.87 113.3,22.82 113.3,18.85 113.53,18.62 114.85,18.62 115.1,18.87 115.1,19.57 114.49,20.18 114.49,22.8
(no net) on BOTTOM: 82.75,22.87 81.68,22.87 81.63,22.82 81.63,18.85 81.86,18.62 83.18,18.62 83.44,18.87 83.44,19.84 82.83,20.45 82.83,22.8
(no net) on BOTTOM: 25.27,29.34 25.27,30.99 25.02,31.24 23.49,31.24 23.24,30.99 23.24,29.34 23.44,29.13 25.07,29.13
(no net) on BOTTOM: 110.96,22.87 112.03,22.87 112.08,22.82 112.08,18.85 111.85,18.62 110.53,18.62 110.28,18.87 110.28,19.91 110.89,20.52 110.89,22.8
(no net) on BOTTOM: 14.5,23.6 15.57,23.6 15.62,23.65 15.62,28.35 15.44,28.52 13.77,28.52 13.59,28.35 13.59,27.03 13.74,26.87 14.33,26.87 14.43,26.77 14.43,23.67
(no net) on BOTTOM: 89.15,22.87 88.08,22.87 88.03,22.82 88.03,18.85 88.26,18.62 89.58,18.62 89.84,18.87 89.84,19.79 89.23,20.4 89.23,22.8
(no net) on BOTTOM: 79.3,22.87 80.37,22.87 80.42,22.82 80.42,18.85 80.19,18.62 78.87,18.62 78.61,18.87 78.61,19.91 79.22,20.52 79.22,22.8
(no net) on BOTTOM: 22.1,29.34 22.1,30.99 21.84,31.24 20.32,31.24 20.07,30.99 20.07,29.34 20.27,29.13 21.89,29.13
(no net) on BOTTOM: 85.7,22.87 86.77,22.87 86.82,22.82 86.82,18.85 86.59,18.62 85.27,18.62 85.01,18.87 85.01,19.91 85.62,20.52 85.62,22.8
(no net) on BOTTOM: 104.56,22.87 105.63,22.87 105.68,22.82 105.68,18.85 105.45,18.62 104.13,18.62 103.88,18.87 103.88,19.78 104.49,20.39 104.49,22.8
FS84_BUCK1_SW on TOP: 135.05,43.89 135.23,43.89 135.28,43.94 135.28,45.24 135.51,45.47 135.51,47.8 133.25,47.8 133.25,46.63 133.91,45.97 134.11,45.97 134.82,45.26 134.82,44.96 135,44.78 135,43.94
FS84_BUCK3_SW on TOP: 135.48,36.86 135.48,35.43 135.94,34.98 135.94,34.37 136.91,33.4 139.07,33.4 139.12,33.45 139.12,34.37 139.07,34.42 137.26,34.42 135.79,35.89 135.79,36.86
FS84_PRE_CSP on TOP: 125.35,53.98 125.86,54.48 125.86,58.19 125.48,58.57 117.7,58.57 117.25,58.12 117.25,54.46 117.73,53.98
FS84_PRE_SW on TOP: 117.93,43.43 123.27,43.43 123.27,46.18 123.57,46.48 125.73,46.48 126.62,45.59 126.62,41.91 126.34,41.63 123.83,41.63 123.83,40.89 127.64,40.89 128.93,42.19 128.93,43.03 129.16,43.26 130.51,43.26 130.68,43.43 130.68,44.07 129.12,45.62 129.12,48.18 125.48,51.82 118.82,51.82 117.7,50.7 117.7,43.66
MAX96789_CAPVDD1 on L4_MIX_2: 39.62,50.8 43.05,50.8 43.38,51.13 43.38,52.14 43.2,52.32 39.6,52.32 39.32,52.04 39.32,51.1
MAX96789_CAPVDD2 on L4_MIX_2: 26.29,53.72 26.29,51.74 26.9,51.13 29.72,51.13 30.86,52.27 31.47,52.27 31.78,51.97 32.41,51.97 32.64,52.2 32.64,53.49 32,54.13 26.7,54.13
Net_9 on TOP (solid shape): 25.05,69.81 25.04,69.71 25.04,69.61 25.22,68.78 25.74,68.09 25.74,67.61 23.39,67.61 23.39,69.81
Net_9 on TOP (solid shape): 40.72,67.61 38.37,67.61 38.37,68.09 38.88,68.78 39.07,69.61 39.06,69.71 39.06,69.81 40.72,69.81
Net_9 on TOP (solid shape): 82.86,69.81 82.85,69.71 82.85,69.61 83.03,68.78 83.55,68.09 83.55,67.61 81.2,67.61 81.2,69.81
Net_9 on TOP (solid shape): 98.52,67.61 96.17,67.61 96.17,68.09 96.69,68.78 96.87,69.61 96.87,69.71 96.86,69.81 98.52,69.81
Net_9 on TOP (solid shape): 37.27,71.61 35.07,71.61 33.65,71.03 33.07,69.61 33.07,62.41 31.07,62.41 31.07,69.61 30.48,71.03 29.07,71.61 27.07,71.61 27.07,72.71 37.27,72.71
Net_9 on TOP (solid shape): 95.07,71.61 92.87,71.61 91.46,71.03 90.87,69.61 90.87,62.41 88.87,62.41 88.87,69.61 88.29,71.03 86.87,71.61 84.87,71.61 84.87,72.71 95.07,72.71
VPI on TOP: 123.95,37.08 123.95,40.26 123.32,40.89 123.32,42.93 113.79,42.93 113.41,42.55 113.41,39.5 113.54,39.37 117.6,39.37 118.49,38.48 118.49,37.34 118.87,36.96 123.83,36.96

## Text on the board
BOTTOM: 09 | L6_SS | 170-55264 REV B
Board Geometry/Soldermask Bottom: 10 | SECONDARY SOLDERMASK
Ref Des/Silkscreen Bottom: 700-XXXXX-X | SCH-XXXXX-X | 11 | SECONDARY SILKSCREEN
User.Comments: 1 OF 1 | TEST PROBE | 1/1 | 1 | 2
TOP: 04 | L1_PS
Board Geometry/Soldermask Top: 03 | PRIMARY SOLDERMASK
Ref Des/Silkscreen Top: 1V8 | GND | SCL | MFP17 | MFP18 | SDA | G2 | G3 | G4 | G6 | G7 | G1 | G5 | G8 | G9 | G10 | G11 | G14 | G15 | 3V3 | I2C | LVDS0 | I2C1 | LVDS1 | A | CFG2 | MFP8 | LOCK | MFP2 | CFG0 | MFP7 | MFP9 | ERRB | MFP3 | CFG1 | MFP10 | MFP12 | MFP11 | ERR_B | G13 | G12 | SERIALISER | DESERIALISER | 02 | PRIMARY SILKSCREEN | IMX-DSI-SDSB
L2_GND_1: 05 | L2_GND_1
L3_MIX_1: 06 | L3_MIX_1
L4_MIX_2: 07 | L4_MIX_2
L5_GND_2: 08 | L5_GND_2
XSECTION_CHART: L3 L3_MIX_1 CONDUCTOR - 1/2OZ_COPPER 0.6 MIL | *  DIELECTRIC - TU768-CORE_0.1MM 3.94 MIL | *  SURFACE - AIR 0 MIL | *  DIELECTRIC - SOLDERMASK 1.5 MIL | L1 TOP CONDUCTOR - 1/2OZ_COPPER_PLATED 1.5 MIL | *  DIELECTRIC - TU768-PP_3313 3.48 MIL | L2 L2_GND_1 PLANE - 1/2OZ_COPPER 0.6 MIL | *  DIELECTRIC - TU768-PP_1080X2 5.19 MIL | *  DIELECTRIC - TU768-CORE_NOCOPPER 27.95 MIL | L5 L5_GND_2 PLANE - 1/2OZ_COPPER 0.6 MIL | L6 BOTTOM CONDUCTOR - 1/2OZ_COPPER_PLATED 1.5 MIL | L4 L4_MIX_2 CONDUCTOR - 1/2OZ_COPPER 0.6 MIL | DESIGN CROSS SECTION CHART | ___________________________ | TOTAL THICKNESS 61.57 MIL | 1-6
DIMENSION: SCALE: NONE | ALL VALUES ARE FINISHED VALUES | BOARD THICKNESS TOLERANCE +/-10% | 1/3 PCB THICKNESS | BREAKING EDGE | BOTH SIDE 2x | DETAIL-C | TOP SIDE | BOT SIDE | 19 | 16 | 22 | DETAIL | IMPEDANCE REQUIREMENTS | IMPEDANCE TOLERANCE IS 10% | LAYER STACKUP | PRIMARY DATUM | GRID ORIGIN | VCUT | B | A
PASTEMASK_TOP: 01 | PRIMARY PASTEMASK
User.5: 12 | SECONDARY PASTEMASK
User.10: OF 12
User.13: 22. THIS FAB_VIAFILL.ART SHOWS LOCATIONS OF VIA-IN-PAD TO BE FILLED. | 1/1 | 2
User.14: 24. | 1/1 | 3 | CAD DESIGNER: DELETE THIS FAB PAGE IF BACKDRILL IS NOT USED ON THIS DESIGN. | FAB SUPPLIER: DISREGARD THIS PAGE IF BACKDRILL REQUIRMENT IS NOT PROVIDED.
User.15: 08-03-23 | KINJALK | LING.C | ABHISHEK | B | I2C Updated
User.19: TOP TO LAYER X | BACK DRILL REFERENCE | BOTTOM TO LAYER X | LAYER X | MUST CUT LAYER | LAYER X+1 | MUST NOT CUT LAYER | LAYER X-1
User.20: FIGURE | FINISHED_SIZE | 10.0 | 10.1 | 28.0 | 32.0 | 40.0 | 44.0 | 45.0 | 47.0 | 63.0 | 69.0 | 126.0 | 61.0 | DRILL CHART: TOP to BOTTOM | ALL UNITS ARE IN MILS | TOLERANCE_DRILL | +0.0/-10.0 | +0.0/-10.1 | +2.0/-2.0 | +3.0/-3.0 | +4.0/-4.0 | PLATED | NON-PLATED | QTY | 1020 | 89 | 8 | 24 | 84 | 2 | 9 | 12 | 1274 | TOTAL HOLES:
